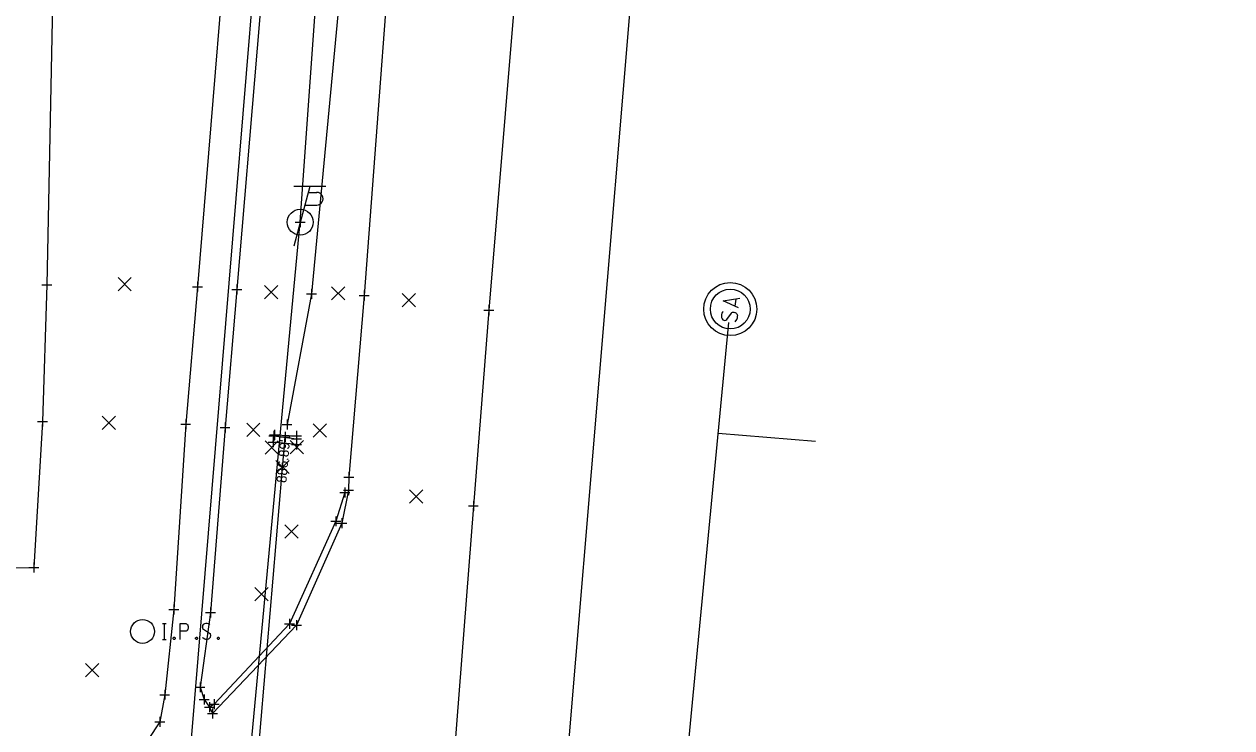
# Model space of a CAD drawing. Extents: x 1380440 to 1381945, y 468756 to 470369.
# Drawn here: x 1381544.2 to 1381665.6, y 469836.8 to 469907.6 of the extents above; entities that cross this region are included whole.
import ezdxf

# ---------------------------------------------------------------- set-up
doc = ezdxf.new("R2010")
doc.units = 0
for name, color, linetype in [('DR_P_Headwall', 7, 'Continuous'), ('DR_X_Cells', 7, 'Continuous'), ('DV_X_Lot_Line', 7, 'Continuous'), ('GE_P_Driveway_CL', 7, 'Continuous'), ('PM_X_CL_Double_Solid', 7, 'Continuous'), ('PV_P_Curb', 7, 'Continuous'), ('PV_P_Curb_Ramp', 7, 'Continuous'), ('PV_P_EOP', 7, 'Continuous'), ('PV_P_Saw_Cut_Line', 7, 'Continuous'), ('PV_P_Walk', 7, 'Continuous'), ('PV_X_COP', 7, 'Continuous'), ('RW_P_Esmt_TMP', 7, 'Continuous'), ('SC_Scratch1', 7, 'Continuous'), ('SC_Scratch3', 7, 'Continuous'), ('SC_Shading1', 7, 'Continuous'), ('SH_Named_Boundary', 7, 'Continuous'), ('UT_X_Gas', 7, 'Continuous'), ('UT_X_Overhead_Combined', 7, 'Continuous'), ('UT_X_Sanitary_Line', 7, 'Continuous'), ('UT_X_Water', 7, 'Continuous'), ('X-CL', 7, 'Continuous')]:
    doc.layers.add(name, color=color, linetype=linetype)

msp = doc.modelspace()

# ---------------------------------------------------------------- linework, layer by layer
at = {"layer": 'DR_P_Headwall'}
for points in [[(1381595.25, 470241), (1381595.01, 470239.38), (1381594.79, 470235.56), (1381591.94, 470203.13), (1381590.15, 470180.15), (1381585.84, 470126.11), (1381581.45, 470072.84), (1381577.22, 470021.47), (1381573.16, 469971.68), (1381569.7, 469929.43), (1381565.6, 469880.89), (1381564.41, 469867), (1381562.95, 469848.39), (1381561.9, 469840.88)], [(1381542.56, 470237.64), (1381568.34, 470236.69), (1381578.51, 470236.26), (1381584.49, 470236.02), (1381590.64, 470235.62), (1381587.95, 470203.42), (1381586.62, 470180.46), (1381581.93, 470126.46), (1381577.65, 470073.24), (1381573.2, 470021.54), (1381569.15, 469971.74), (1381565.64, 469929.65), (1381561.64, 469881.16), (1381560.46, 469867.32), (1381559.27, 469848.71), (1381558.35, 469840.14)]]:
    msp.add_lwpolyline(points, dxfattribs=at)
at = {"layer": 'DR_X_Cells'}
msp.add_lwpolyline([(1381576.45, 469860.47), (1381575.55, 469857.57), (1381570.89, 469847.25), (1381563.33, 469839.19), (1381562.85, 469838.89)], dxfattribs=at)
at = {"layer": 'DV_X_Lot_Line'}
msp.add_lwpolyline([(1381569.38, 469866.27), (1381571.6, 469866.16)], dxfattribs=at)
at = {"layer": 'GE_P_Driveway_CL'}
for p, q in [((1381553.66, 469880.73), (1381554.99, 469882.07)), ((1381553.66, 469882.07), (1381554.99, 469880.73)), ((1381568.38, 469879.95), (1381569.72, 469881.29)), ((1381568.38, 469881.29), (1381569.72, 469879.95)), ((1381575.11, 469879.83), (1381576.44, 469881.16)), ((1381575.11, 469881.16), (1381576.44, 469879.83)), ((1381582.21, 469879.12), (1381583.54, 469880.46)), ((1381582.21, 469880.46), (1381583.54, 469879.12)), ((1381552.08, 469866.8), (1381553.41, 469868.13)), ((1381552.08, 469868.13), (1381553.41, 469866.8)), ((1381566.59, 469866.09), (1381567.92, 469867.43)), ((1381566.59, 469867.43), (1381567.92, 469866.09)), ((1381573.28, 469866.03), (1381574.61, 469867.37)), ((1381573.28, 469867.37), (1381574.61, 469866.03)), ((1381568.43, 469864.32), (1381569.76, 469865.65)), ((1381568.43, 469865.65), (1381569.76, 469864.32)), ((1381570.96, 469864.35), (1381572.29, 469865.68)), ((1381570.96, 469865.68), (1381572.29, 469864.35)), ((1381569.51, 469862.37), (1381570.84, 469863.7)), ((1381569.51, 469863.7), (1381570.84, 469862.37)), ((1381582.96, 469859.41), (1381584.29, 469860.75)), ((1381582.96, 469860.75), (1381584.29, 469859.41)), ((1381570.42, 469855.88), (1381571.76, 469857.21)), ((1381570.42, 469857.21), (1381571.76, 469855.88)), ((1381567.42, 469849.58), (1381568.76, 469850.92)), ((1381567.42, 469850.92), (1381568.76, 469849.58)), ((1381550.4, 469841.93), (1381551.73, 469843.26)), ((1381550.4, 469843.26), (1381551.73, 469841.93))]:
    msp.add_line(p, q, dxfattribs=at)
at = {"layer": 'PM_X_CL_Double_Solid'}
msp.add_lwpolyline([(1381618.76, 470220.14), (1381616.92, 470200.19), (1381615.1, 470178.83), (1381610.95, 470124.78), (1381606.49, 470071.23), (1381602.26, 470019.36), (1381598.18, 469969.8), (1381595.01, 469928.06), (1381590.91, 469878.81), (1381589.36, 469859.11), (1381585.99, 469815.58), (1381581.29, 469760.78), (1381580.3, 469747.86), (1381578.72, 469729.45), (1381576.78, 469708.95), (1381575.29, 469689.79), (1381572.76, 469657.56), (1381569.36, 469615.7), (1381565.36, 469567.23), (1381561.16, 469537.52), (1381558.94, 469486.81), (1381555.39, 469442.03), (1381550.97, 469391.02)], dxfattribs=at)
at = {"layer": 'PV_P_Curb'}
msp.add_lwpolyline([(1381599.49, 470202.78), (1381597.12, 470179.51), (1381597.25, 470175.53), (1381597.2, 470175.03), (1381592.57, 470125.52), (1381589.1, 470072.43), (1381585.65, 470022.01), (1381581.71, 469971.4), (1381577.66, 469928.75), (1381573.1, 469880.44), (1381570.64, 469867.29)], dxfattribs=at)
at = {"layer": 'PV_P_Curb_Ramp'}
for p, q in [((1381613.19, 469879.16), (1381613.19, 469879.16)), ((1381615.17, 469878.91), (1381615.17, 469878.91)), ((1381615.17, 469878.91), (1381615.17, 469878.91)), ((1381615.17, 469878.91), (1381615.17, 469878.91)), ((1381617.16, 469878.66), (1381617.16, 469878.66))]:
    msp.add_line(p, q, dxfattribs=at)
msp.add_circle((1381615.17, 469878.91), 2, dxfattribs=at)
at = {"layer": 'PV_P_EOP'}
for points in [[(1381615.99, 469879.02), (1381614.47, 469879.72), (1381616.12, 469880)], [(1381615.73, 469879.92), (1381615.63, 469879.19)], [(1381614.45, 469878.66), (1381614.42, 469878.64), (1381614.39, 469878.61), (1381614.34, 469878.5), (1381614.3, 469878.37), (1381614.28, 469878.27), (1381614.28, 469878.23), (1381614.3, 469878.06), (1381614.35, 469877.91), (1381614.44, 469877.81), (1381614.54, 469877.78), (1381614.61, 469877.77), (1381614.72, 469877.78), (1381614.82, 469877.87), (1381615.28, 469878.51), (1381615.34, 469878.56), (1381615.39, 469878.58), (1381615.47, 469878.6), (1381615.54, 469878.59), (1381615.62, 469878.57), (1381615.67, 469878.55), (1381615.73, 469878.52), (1381615.77, 469878.48), (1381615.81, 469878.45), (1381615.84, 469878.41), (1381615.86, 469878.37), (1381615.88, 469878.32), (1381615.89, 469878.28), (1381615.88, 469878.17), (1381615.86, 469877.99), (1381615.82, 469877.88), (1381615.71, 469877.73), (1381615.63, 469877.64)]]:
    msp.add_lwpolyline(points, dxfattribs=at)
for radius in [2.67, 2]:
    msp.add_circle((1381615.17, 469878.91), radius, dxfattribs=at)
at = {"layer": 'PV_P_Saw_Cut_Line'}
for p, q in [((1381570.47, 469866.55), (1381570.47, 469865.55)), ((1381569.97, 469866.05), (1381570.97, 469866.05)), ((1381570.47, 469866.05), (1381570.47, 469866.05))]:
    msp.add_line(p, q, dxfattribs=at)
at = {"layer": 'PV_P_Walk'}
for points in [[(1381558.14, 469847.3), (1381558.5, 469847.3)], [(1381558.32, 469845.7), (1381558.32, 469847.3)], [(1381559.89, 469845.7), (1381559.89, 469847.3), (1381560.42, 469847.3), (1381560.47, 469847.29), (1381560.55, 469847.26), (1381560.58, 469847.24), (1381560.61, 469847.21), (1381560.66, 469847.15), (1381560.69, 469847.08), (1381560.71, 469846.98), (1381560.71, 469846.83), (1381560.7, 469846.78), (1381560.68, 469846.71), (1381560.64, 469846.62), (1381560.59, 469846.58), (1381560.56, 469846.56), (1381560.5, 469846.53), (1381560.42, 469846.52), (1381559.89, 469846.52)], [(1381562.9, 469847.18), (1381562.87, 469847.21), (1381562.84, 469847.24), (1381562.74, 469847.27), (1381562.62, 469847.3), (1381562.53, 469847.3), (1381562.5, 469847.3), (1381562.36, 469847.26), (1381562.23, 469847.18), (1381562.16, 469847.08), (1381562.14, 469846.98), (1381562.14, 469846.91), (1381562.16, 469846.81), (1381562.25, 469846.72), (1381562.85, 469846.34), (1381562.91, 469846.29), (1381562.93, 469846.24), (1381562.95, 469846.16), (1381562.95, 469846.09), (1381562.94, 469846.01), (1381562.93, 469845.96), (1381562.91, 469845.9), (1381562.88, 469845.85), (1381562.86, 469845.81), (1381562.83, 469845.77), (1381562.8, 469845.75), (1381562.75, 469845.72), (1381562.72, 469845.71), (1381562.62, 469845.7), (1381562.47, 469845.7), (1381562.37, 469845.72), (1381562.22, 469845.81), (1381562.14, 469845.89)], [(1381558.14, 469845.7), (1381558.5, 469845.7)], [(1381559.28, 469845.91), (1381559.34, 469845.91), (1381559.37, 469845.89), (1381559.4, 469845.84), (1381559.4, 469845.77), (1381559.37, 469845.72), (1381559.34, 469845.7), (1381559.28, 469845.7), (1381559.25, 469845.72), (1381559.21, 469845.77), (1381559.21, 469845.84), (1381559.25, 469845.89), (1381559.28, 469845.91)], [(1381561.53, 469845.91), (1381561.58, 469845.91), (1381561.62, 469845.89), (1381561.65, 469845.84), (1381561.65, 469845.77), (1381561.62, 469845.72), (1381561.58, 469845.7), (1381561.53, 469845.7), (1381561.5, 469845.72), (1381561.46, 469845.77), (1381561.46, 469845.84), (1381561.5, 469845.89), (1381561.53, 469845.91)], [(1381563.71, 469845.91), (1381563.77, 469845.91), (1381563.8, 469845.89), (1381563.83, 469845.84), (1381563.83, 469845.77), (1381563.8, 469845.72), (1381563.77, 469845.7), (1381563.71, 469845.7), (1381563.68, 469845.72), (1381563.65, 469845.77), (1381563.65, 469845.84), (1381563.68, 469845.89), (1381563.71, 469845.91)]]:
    msp.add_lwpolyline(points, dxfattribs=at)
msp.add_circle((1381556.13, 469846.5), 1.2, dxfattribs=at)
at = {"layer": 'PV_X_COP'}
for p, q in [((1381572.93, 469891.24), (1381571.32, 469885.24)), ((1381574.53, 469891.24), (1381571.33, 469891.24)), ((1381572.77, 469890.64), (1381573.62, 469890.64)), ((1381572.43, 469889.37), (1381573.62, 469889.37))]:
    msp.add_line(p, q, dxfattribs=at)
msp.add_circle((1381571.97, 469887.64), 1.3, dxfattribs=at)
msp.add_arc((1381573.63, 469890), 0.638, 268.8767, 91.1233, dxfattribs=at)
at = {"layer": 'RW_P_Esmt_TMP'}
for points in [[(1381575.39, 470244.04), (1381576.99, 470244.17), (1381579.54, 470245.54), (1381580.63, 470247.96), (1381580.96, 470249.54), (1381591.47, 470243.59), (1381595.25, 470241), (1381599.72, 470235.67), (1381603.29, 470229.19), (1381604.88, 470222.31), (1381604.1, 470201.73), (1381602.36, 470179.43), (1381598.63, 470125.51), (1381593.59, 470071.89), (1381589.53, 470020.65), (1381585.49, 469971.09), (1381582.04, 469928.84), (1381578.38, 469880.28), (1381576.86, 469862.02), (1381576.83, 469860.71), (1381576.16, 469857.38), (1381571.59, 469847.12), (1381563.14, 469838.25)], [(1381550.16, 469977.26), (1381547.52, 469931.2), (1381546.52, 469881.36), (1381546.07, 469867.59), (1381545.21, 469852.93)], [(1381558.35, 469840.14), (1381557.85, 469837.4), (1381556.7, 469835.65), (1381547.32, 469831.26), (1381539.24, 469830.04), (1381534.26, 469830.33), (1381533.24, 469830.81), (1381532.35, 469831.75), (1381531.61, 469833.22), (1381528.74, 469838.25), (1381528.06, 469839.33), (1381527.53, 469840.55), (1381527.51, 469841.81), (1381527.73, 469842.93), (1381527.99, 469844.34), (1381528.64, 469852.75), (1381545.21, 469852.93)], [(1381561.9, 469840.88), (1381562.32, 469839.66), (1381562.85, 469838.89), (1381563.14, 469838.25)]]:
    msp.add_lwpolyline(points, dxfattribs=at)
at = {"layer": 'SC_Scratch3'}
msp.add_lwpolyline([(1381569.24, 469865.52), (1381569.32, 469866.15), (1381571.58, 469865.85), (1381571.58, 469865.29)], close=True, dxfattribs=at)
at = {"layer": 'SC_Shading1'}
msp.add_lwpolyline([(1381627.41, 470324.23), (1381625.02, 470294.42), (1381622.34, 470259.95), (1381618.76, 470220.14), (1381616.92, 470200.19), (1381615.1, 470178.83), (1381610.95, 470124.78), (1381606.49, 470071.23), (1381602.26, 470019.36), (1381598.18, 469969.8), (1381595.01, 469928.06), (1381590.91, 469878.81), (1381589.36, 469859.11), (1381585.99, 469815.58)], dxfattribs=at)
at = {"layer": 'SH_Named_Boundary'}
for p, q in [((1381571.97, 469888.14), (1381571.97, 469887.14)), ((1381571.97, 469888.14), (1381571.97, 469887.14)), ((1381571.47, 469887.64), (1381572.47, 469887.64)), ((1381571.47, 469887.64), (1381572.47, 469887.64)), ((1381571.97, 469887.64), (1381571.97, 469887.64)), ((1381571.97, 469887.64), (1381571.97, 469887.64)), ((1381546.02, 469881.36), (1381547.02, 469881.36)), ((1381546.52, 469881.86), (1381546.52, 469880.86)), ((1381546.52, 469881.36), (1381546.52, 469881.36)), ((1381561.14, 469881.16), (1381562.14, 469881.16)), ((1381561.64, 469881.66), (1381561.64, 469880.66)), ((1381561.64, 469881.16), (1381561.64, 469881.16)), ((1381565.1, 469880.89), (1381566.1, 469880.89)), ((1381565.6, 469881.39), (1381565.6, 469880.39)), ((1381565.6, 469880.89), (1381565.6, 469880.89)), ((1381573.1, 469880.94), (1381573.1, 469879.94)), ((1381578.38, 469880.78), (1381578.38, 469879.78)), ((1381572.6, 469880.44), (1381573.6, 469880.44)), ((1381573.1, 469880.44), (1381573.1, 469880.44)), ((1381577.88, 469880.28), (1381578.88, 469880.28)), ((1381578.38, 469880.28), (1381578.38, 469880.28)), ((1381590.41, 469878.81), (1381591.41, 469878.81)), ((1381590.91, 469879.31), (1381590.91, 469878.31)), ((1381590.91, 469878.81), (1381590.91, 469878.81)), ((1381545.57, 469867.59), (1381546.57, 469867.59)), ((1381546.07, 469868.09), (1381546.07, 469867.09)), ((1381546.07, 469867.59), (1381546.07, 469867.59)), ((1381560.46, 469867.82), (1381560.46, 469866.82)), ((1381564.41, 469867.5), (1381564.41, 469866.5)), ((1381570.64, 469867.79), (1381570.64, 469866.79)), ((1381559.96, 469867.32), (1381560.96, 469867.32)), ((1381560.46, 469867.32), (1381560.46, 469867.32)), ((1381563.91, 469867), (1381564.91, 469867)), ((1381564.41, 469867), (1381564.41, 469867)), ((1381568.88, 469866.27), (1381569.88, 469866.27)), ((1381569.32, 469866.65), (1381569.32, 469865.65)), ((1381569.38, 469866.77), (1381569.38, 469865.77)), ((1381569.38, 469866.27), (1381569.38, 469866.27)), ((1381570.14, 469867.29), (1381571.14, 469867.29)), ((1381570.64, 469867.29), (1381570.64, 469867.29)), ((1381571.58, 469866.35), (1381571.58, 469865.35)), ((1381571.6, 469866.66), (1381571.6, 469865.66)), ((1381568.74, 469865.52), (1381569.74, 469865.52)), ((1381568.82, 469866.15), (1381569.82, 469866.15)), ((1381569.24, 469866.02), (1381569.24, 469865.02)), ((1381569.24, 469865.52), (1381569.24, 469865.52)), ((1381569.32, 469866.15), (1381569.32, 469866.15)), ((1381571.08, 469865.85), (1381572.08, 469865.85)), ((1381571.08, 469865.29), (1381572.08, 469865.29)), ((1381571.1, 469866.16), (1381572.1, 469866.16)), ((1381571.58, 469865.85), (1381571.58, 469865.85)), ((1381571.58, 469865.79), (1381571.58, 469864.79)), ((1381571.58, 469865.29), (1381571.58, 469865.29)), ((1381571.6, 469866.16), (1381571.6, 469866.16)), ((1381576.86, 469862.52), (1381576.86, 469861.52)), ((1381576.36, 469862.02), (1381577.36, 469862.02)), ((1381576.86, 469862.02), (1381576.86, 469862.02)), ((1381575.95, 469860.47), (1381576.95, 469860.47)), ((1381576.33, 469860.71), (1381577.33, 469860.71)), ((1381576.45, 469860.97), (1381576.45, 469859.97)), ((1381576.45, 469860.47), (1381576.45, 469860.47)), ((1381576.83, 469861.21), (1381576.83, 469860.21)), ((1381576.83, 469860.71), (1381576.83, 469860.71)), ((1381588.86, 469859.11), (1381589.86, 469859.11)), ((1381589.36, 469859.61), (1381589.36, 469858.61)), ((1381589.36, 469859.11), (1381589.36, 469859.11)), ((1381575.55, 469858.07), (1381575.55, 469857.07)), ((1381575.55, 469858.07), (1381575.55, 469857.07)), ((1381576.16, 469857.88), (1381576.16, 469856.88)), ((1381576.16, 469857.88), (1381576.16, 469856.88)), ((1381575.05, 469857.57), (1381576.05, 469857.57)), ((1381575.05, 469857.57), (1381576.05, 469857.57)), ((1381575.55, 469857.57), (1381575.55, 469857.57)), ((1381575.55, 469857.57), (1381575.55, 469857.57)), ((1381575.66, 469857.38), (1381576.66, 469857.38)), ((1381575.66, 469857.38), (1381576.66, 469857.38)), ((1381576.16, 469857.38), (1381576.16, 469857.38)), ((1381576.16, 469857.38), (1381576.16, 469857.38)), ((1381544.71, 469852.93), (1381545.71, 469852.93)), ((1381544.71, 469852.93), (1381545.71, 469852.93)), ((1381545.21, 469853.43), (1381545.21, 469852.43)), ((1381545.21, 469853.43), (1381545.21, 469852.43)), ((1381545.21, 469852.93), (1381545.21, 469852.93)), ((1381545.21, 469852.93), (1381545.21, 469852.93)), ((1381559.27, 469849.21), (1381559.27, 469848.21)), ((1381558.77, 469848.71), (1381559.77, 469848.71)), ((1381559.27, 469848.71), (1381559.27, 469848.71)), ((1381562.45, 469848.39), (1381563.45, 469848.39)), ((1381562.95, 469848.89), (1381562.95, 469847.89)), ((1381562.95, 469848.39), (1381562.95, 469848.39)), ((1381570.39, 469847.25), (1381571.39, 469847.25)), ((1381570.89, 469847.75), (1381570.89, 469846.75)), ((1381570.89, 469847.25), (1381570.89, 469847.25)), ((1381571.09, 469847.12), (1381572.09, 469847.12)), ((1381571.59, 469847.62), (1381571.59, 469846.62)), ((1381571.59, 469847.12), (1381571.59, 469847.12)), ((1381561.4, 469840.88), (1381562.4, 469840.88)), ((1381561.4, 469840.88), (1381562.4, 469840.88)), ((1381561.9, 469841.38), (1381561.9, 469840.38)), ((1381561.9, 469841.38), (1381561.9, 469840.38)), ((1381561.9, 469840.88), (1381561.9, 469840.88)), ((1381561.9, 469840.88), (1381561.9, 469840.88)), ((1381557.85, 469840.14), (1381558.85, 469840.14)), ((1381557.85, 469840.14), (1381558.85, 469840.14)), ((1381558.35, 469840.64), (1381558.35, 469839.64)), ((1381558.35, 469840.64), (1381558.35, 469839.64)), ((1381558.35, 469840.14), (1381558.35, 469840.14)), ((1381558.35, 469840.14), (1381558.35, 469840.14)), ((1381561.82, 469839.66), (1381562.82, 469839.66)), ((1381562.32, 469840.16), (1381562.32, 469839.16)), ((1381562.32, 469839.66), (1381562.32, 469839.66)), ((1381563.33, 469839.69), (1381563.33, 469838.69)), ((1381563.33, 469839.69), (1381563.33, 469838.69)), ((1381562.35, 469838.89), (1381563.35, 469838.89)), ((1381562.35, 469838.89), (1381563.35, 469838.89)), ((1381562.83, 469839.19), (1381563.83, 469839.19)), ((1381562.83, 469839.19), (1381563.83, 469839.19)), ((1381562.85, 469839.39), (1381562.85, 469838.39)), ((1381562.85, 469839.39), (1381562.85, 469838.39)), ((1381562.85, 469838.89), (1381562.85, 469838.89)), ((1381562.85, 469838.89), (1381562.85, 469838.89)), ((1381563.14, 469838.75), (1381563.14, 469837.75)), ((1381563.14, 469838.75), (1381563.14, 469837.75)), ((1381563.33, 469839.19), (1381563.33, 469839.19)), ((1381563.33, 469839.19), (1381563.33, 469839.19)), ((1381557.35, 469837.4), (1381558.35, 469837.4)), ((1381557.85, 469837.9), (1381557.85, 469836.9)), ((1381557.85, 469837.4), (1381557.85, 469837.4)), ((1381562.64, 469838.25), (1381563.64, 469838.25)), ((1381562.64, 469838.25), (1381563.64, 469838.25)), ((1381563.14, 469838.25), (1381563.14, 469838.25)), ((1381563.14, 469838.25), (1381563.14, 469838.25))]:
    msp.add_line(p, q, dxfattribs=at)
at = {"layer": 'UT_X_Gas'}
msp.add_lwpolyline([(1381485.9, 468926.41), (1381594.27, 470237.89), (1380558, 470279.29)], dxfattribs=at)
at = {"layer": 'UT_X_Overhead_Combined'}
msp.add_lwpolyline([(1381540.8, 469054.26), (1381515.28, 469203.1), (1381529.17, 469390.12), (1381543.86, 469565.78), (1381559.77, 469757.41), (1381571.97, 469887.64), (1381581.26, 470018.2), (1381595.79, 470220.83), (1381665.56, 470247.4)], dxfattribs=at)
at = {"layer": 'UT_X_Sanitary_Line'}
for p, q in [((1381599.15, 469712.1), (1381615.04, 469877.56)), ((1381623.75, 469865.6), (1381613.97, 469866.39))]:
    msp.add_line(p, q, dxfattribs=at)
at = {"layer": 'UT_X_Water'}
msp.add_line((1381545.41, 469194.71), (1381630.26, 470209.69), dxfattribs=at)
at = {"layer": 'X-CL'}
msp.add_line((1381562.3, 469770.76), (1381570.47, 469866.05), dxfattribs=at)

# ---------------------------------------------------------------- texts
at = {"layer": 'SC_Scratch1'}
msp.add_text("886.89'", height=1, rotation=85.1034, dxfattribs=at).set_placement((1381570.57, 469861.4))

doc.saveas('drawing.dxf')
